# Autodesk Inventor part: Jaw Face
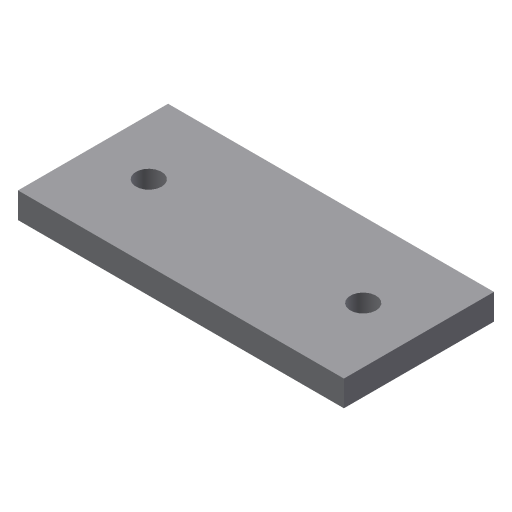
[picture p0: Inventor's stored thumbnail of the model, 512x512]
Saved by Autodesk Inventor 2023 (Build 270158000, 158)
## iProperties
Created: 2002-02
Part Number: Jaw Face
Document SubType Name: Modeling
Designer: ***
Density: 1 g/cm^3
Material: Generic
Appearance: Default
Control State: 0
Master: False
Checked Out: False
Shininess: 77.0
Length Units: 11269
Angle Units: 11279
Time Units: 11290
Mass Units: 11283
Length Display Precision: 3
Angle Display Precision: 2
Compacted: True
Density: 0.0
Volumn: 0.0
Area: 0.0
PropertySet Name: Model Information
Author: ***
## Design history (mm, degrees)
sketch "Sketch1"
  geometry: L1 (-79.661, -8.43)-(-3.661, -8.43); L2 (-3.661, -8.43)-(-3.661, -43.43); L3 (-3.661, -43.43)-(-79.661, -43.43); L4 (-79.661, -43.43)-(-79.661, -8.43); C1 r 3 at (-66.661, -25.93); C2 r 3 at (-16.661, -25.93)
  constraints: 8 end point, 2 centre point, 2 parallel, 1 equal radius, 1 horizontal, 1 perpendicular
  dimensions: "d0" = 76 distance of L2.end L3.end; "d1" = 6 diameter of C1; "d2" = 50 distance of C2.centre C1.centre; "d3" = 35 distance of L1.end L2.end; "d4" = 17.5 distance from line of L3 C2.centre; "d5" = 13 distance from line of L2 C2.centre; "d6" = 13 distance from line of L4 C1.centre
extrude "Extrusion1" new body sketch "Sketch1" stored distance "d7" = 6; taper "d8" = 0 deg
body "Solid1"
